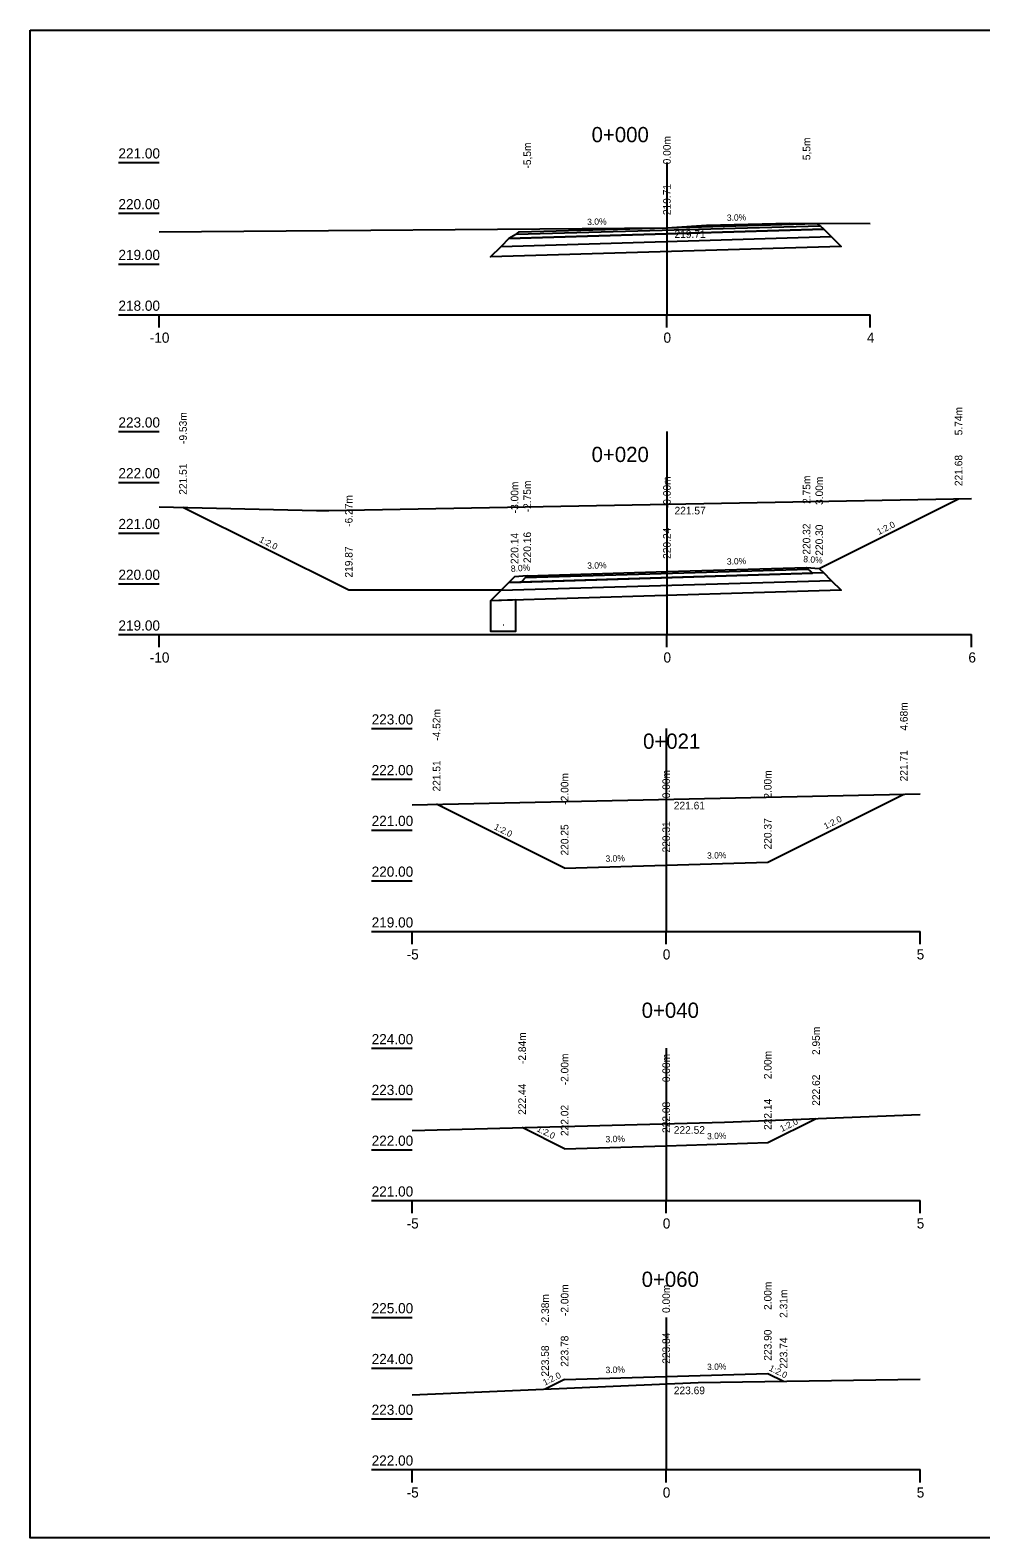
# Model space of a CAD drawing. Extents: x -577111.4 to -577069.4, y -1164371.9 to -1164342.2.
# Drawn here: x -577111.42 to -577092.7, y -1164371.89 to -1164342.19 of the extents above; entities that cross this region are included whole.
import ezdxf

# ---------------------------------------------------------------- set-up
doc = ezdxf.new("R2010")
doc.units = 0
for name, color, linetype in [('16', 7, 'Continuous'), ('21', 7, 'Continuous'), ('28', 7, 'Continuous'), ('59', 7, 'Continuous'), ('Body pricny rez', 7, 'Continuous'), ('Popis pricneho profilu', 7, 'Continuous'), ('Rámy', 7, 'Continuous')]:
    doc.layers.add(name, color=color, linetype=linetype)

msp = doc.modelspace()

# ---------------------------------------------------------------- linework, layer by layer
for points in [[(-577108.878, -1164346.165), (-577098.879, -1164346.086), (-577098.097, -1164346.034), (-577096.456, -1164345.995), (-577094.878, -1164345.998)], [(-577108.878, -1164351.583), (-577105.776, -1164351.655), (-577105.533, -1164351.657), (-577092.878, -1164351.419)], [(-577102.143, -1164353.226), (-577105.143, -1164353.226), (-577108.407, -1164351.594)], [(-577095.878, -1164352.795), (-577093.135, -1164351.424)], [(-577102.1, -1164353.907), (-577102.099, -1164353.907)], [(-577103.892, -1164357.45), (-577093.892, -1164357.234)], [(-577096.892, -1164358.581), (-577094.213, -1164357.241)], [(-577100.892, -1164358.701), (-577103.413, -1164357.44)], [(-577100.892, -1164358.701), (-577098.892, -1164358.641), (-577096.892, -1164358.581)], [(-577103.892, -1164363.865), (-577101.426, -1164363.801), (-577097.746, -1164363.703), (-577093.892, -1164363.55)], [(-577100.892, -1164364.227), (-577101.728, -1164363.809)], [(-577096.892, -1164364.107), (-577095.941, -1164363.631)], [(-577100.892, -1164364.227), (-577098.892, -1164364.167), (-577096.892, -1164364.107)], [(-577103.892, -1164369.078), (-577098.262, -1164368.835), (-577093.892, -1164368.766)], [(-577100.892, -1164368.773), (-577101.276, -1164368.966)], [(-577100.892, -1164368.773), (-577098.892, -1164368.713), (-577096.892, -1164368.653)], [(-577096.892, -1164368.653), (-577096.581, -1164368.809)]]:
    msp.add_lwpolyline(points)
for points in [[(-577098.878, -1164346.086), (-577095.935, -1164345.998), (-577095.856, -1164346.053), (-577101.856, -1164346.221), (-577101.786, -1164346.168)], [(-577095.642, -1164346.259), (-577095.448, -1164346.454), (-577102.35, -1164346.661), (-577102.143, -1164346.454)], [(-577101.989, -1164346.3), (-577102.143, -1164346.454), (-577095.642, -1164346.259), (-577095.788, -1164346.114)], [(-577101.856, -1164346.221), (-577101.989, -1164346.3), (-577095.788, -1164346.114), (-577095.856, -1164346.053)], [(-577101.669, -1164352.982), (-577101.751, -1164353.064), (-577096.011, -1164352.892), (-577096.089, -1164352.814)], [(-577098.878, -1164352.858), (-577096.128, -1164352.775), (-577096.089, -1164352.814), (-577101.669, -1164352.982), (-577101.628, -1164352.94)], [(-577096.128, -1164352.775), (-577095.878, -1164352.795), (-577095.788, -1164352.885), (-577096.011, -1164352.892)], [(-577095.642, -1164353.031), (-577095.448, -1164353.225), (-577102.35, -1164353.432), (-577102.143, -1164353.226)], [(-577101.989, -1164353.071), (-577102.143, -1164353.226), (-577095.642, -1164353.031), (-577095.788, -1164352.885)], [(-577101.628, -1164352.94), (-577101.878, -1164352.96), (-577101.989, -1164353.071), (-577101.751, -1164353.064)], [(-577102.35, -1164353.432), (-577102.35, -1164354.032), (-577101.85, -1164354.032), (-577101.85, -1164353.417)]]:
    msp.add_lwpolyline(points, close=True)
at = {"layer": '16'}
for p, q in [((-577108.878, -1164347.8), (-577094.878, -1164347.8)), ((-577108.878, -1164354.1), (-577092.878, -1164354.1)), ((-577103.892, -1164359.949), (-577093.892, -1164359.949)), ((-577103.892, -1164365.249), (-577093.892, -1164365.249)), ((-577103.892, -1164370.549), (-577093.892, -1164370.549))]:
    msp.add_line(p, q, dxfattribs=at)
at = {"layer": '21'}
for p, q in [((-577109.678, -1164344.8), (-577108.878, -1164344.8)), ((-577109.678, -1164345.8), (-577108.878, -1164345.8)), ((-577109.678, -1164346.8), (-577108.878, -1164346.8)), ((-577109.678, -1164347.8), (-577108.878, -1164347.8)), ((-577109.678, -1164350.1), (-577108.878, -1164350.1)), ((-577109.678, -1164351.1), (-577108.878, -1164351.1)), ((-577109.678, -1164352.1), (-577108.878, -1164352.1)), ((-577109.678, -1164353.1), (-577108.878, -1164353.1)), ((-577109.678, -1164354.1), (-577108.878, -1164354.1)), ((-577104.692, -1164355.949), (-577103.892, -1164355.949)), ((-577104.692, -1164356.949), (-577103.892, -1164356.949)), ((-577104.692, -1164357.949), (-577103.892, -1164357.949)), ((-577104.692, -1164358.949), (-577103.892, -1164358.949)), ((-577104.692, -1164359.949), (-577103.892, -1164359.949)), ((-577104.692, -1164362.249), (-577103.892, -1164362.249)), ((-577104.692, -1164363.249), (-577103.892, -1164363.249)), ((-577104.692, -1164364.249), (-577103.892, -1164364.249)), ((-577104.692, -1164365.249), (-577103.892, -1164365.249)), ((-577104.692, -1164367.549), (-577103.892, -1164367.549)), ((-577104.692, -1164368.549), (-577103.892, -1164368.549)), ((-577104.692, -1164369.549), (-577103.892, -1164369.549)), ((-577104.692, -1164370.549), (-577103.892, -1164370.549))]:
    msp.add_line(p, q, dxfattribs=at)
at = {"layer": '28'}
for p, q in [((-577098.878, -1164344.8), (-577098.878, -1164347.8)), ((-577098.878, -1164350.1), (-577098.878, -1164354.1)), ((-577098.892, -1164355.949), (-577098.892, -1164359.949)), ((-577098.892, -1164362.249), (-577098.892, -1164365.249)), ((-577098.892, -1164367.549), (-577098.892, -1164370.549))]:
    msp.add_line(p, q, dxfattribs=at)
at = {"layer": '59'}
for p, q in [((-577108.878, -1164348.05), (-577108.878, -1164347.8)), ((-577098.878, -1164348.05), (-577098.878, -1164347.8)), ((-577094.878, -1164348.05), (-577094.878, -1164347.8)), ((-577108.878, -1164354.35), (-577108.878, -1164354.1)), ((-577098.878, -1164354.35), (-577098.878, -1164354.1)), ((-577092.878, -1164354.35), (-577092.878, -1164354.1)), ((-577103.892, -1164360.199), (-577103.892, -1164359.949)), ((-577098.892, -1164360.199), (-577098.892, -1164359.949)), ((-577093.892, -1164360.199), (-577093.892, -1164359.949)), ((-577103.892, -1164365.499), (-577103.892, -1164365.249)), ((-577098.892, -1164365.499), (-577098.892, -1164365.249)), ((-577093.892, -1164365.499), (-577093.892, -1164365.249)), ((-577103.892, -1164370.799), (-577103.892, -1164370.549)), ((-577098.892, -1164370.799), (-577098.892, -1164370.549)), ((-577093.892, -1164370.799), (-577093.892, -1164370.549))]:
    msp.add_line(p, q, dxfattribs=at)
at = {"layer": 'Rámy'}
msp.add_line((-577111.416, -1164371.893), (-577111.416, -1164370.752), dxfattribs=at)
msp.add_lwpolyline([(-577111.416, -1164342.193), (-577069.416, -1164342.193), (-577069.416, -1164371.893), (-577111.416, -1164371.893)], close=True, dxfattribs=at)

# ---------------------------------------------------------------- texts
for s, p in [('0+000', (-577100.361, -1164344.4)), ('0+020', (-577100.361, -1164350.7)), ('0+021', (-577099.348, -1164356.349)), ('0+040', (-577099.375, -1164361.649)), ('0+060', (-577099.375, -1164366.949))]:
    msp.add_text(s, height=0.3).set_placement(p)
for rotation, p in [(26.5651, (-577094.704, -1164352.139)), (333.4349, (-577106.917, -1164352.269)), (333.4349, (-577102.295, -1164357.929)), (26.5651, (-577095.751, -1164357.94)), (333.4349, (-577101.452, -1164363.877)), (26.5651, (-577096.614, -1164363.898)), (333.4349, (-577096.879, -1164368.59)), (26.5651, (-577101.282, -1164368.898))]:
    msp.add_text('1:2.0', height=0.125, rotation=rotation).set_placement(p)
at = {"layer": '16'}
for s, rotation, p in [('3.0%', 1.7184, (-577100.446, -1164346.033)), ('3.0%', 1.7184, (-577097.696, -1164345.951)), ('8.0%', 355.4261, (-577096.196, -1164352.67)), ('8.0%', 4.5739, (-577101.946, -1164352.866)), ('3.0%', 1.7184, (-577100.446, -1164352.805)), ('3.0%', 1.7184, (-577097.696, -1164352.722)), ('3.0%', 1.7184, (-577100.085, -1164358.576)), ('3.0%', 1.7184, (-577098.085, -1164358.516)), ('3.0%', 1.7184, (-577100.085, -1164364.103)), ('3.0%', 1.7184, (-577098.085, -1164364.043)), ('3.0%', 1.7184, (-577100.085, -1164368.649)), ('3.0%', 1.7184, (-577098.085, -1164368.589))]:
    msp.add_text(s, height=0.125, rotation=rotation, dxfattribs=at).set_placement(p)
at = {"layer": '21'}
for s, p in [('221.00', (-577109.678, -1164344.72)), ('220.00', (-577109.678, -1164345.72)), ('219.00', (-577109.678, -1164346.72)), ('218.00', (-577109.678, -1164347.72)), ('-10', (-577109.061, -1164348.35)), ('0', (-577098.945, -1164348.35)), ('4', (-577094.94, -1164348.35)), ('223.00', (-577109.678, -1164350.02)), ('222.00', (-577109.678, -1164351.02)), ('221.00', (-577109.678, -1164352.02)), ('220.00', (-577109.678, -1164353.02)), ('219.00', (-577109.678, -1164354.02)), ('-10', (-577109.061, -1164354.65)), ('0', (-577098.945, -1164354.65)), ('6', (-577092.941, -1164354.65)), ('223.00', (-577104.692, -1164355.869)), ('222.00', (-577104.692, -1164356.869)), ('221.00', (-577104.692, -1164357.869)), ('220.00', (-577104.692, -1164358.869)), ('219.00', (-577104.692, -1164359.869)), ('-5', (-577104.003, -1164360.499)), ('0', (-577098.959, -1164360.499)), ('5', (-577093.959, -1164360.499)), ('224.00', (-577104.692, -1164362.169)), ('223.00', (-577104.692, -1164363.169)), ('222.00', (-577104.692, -1164364.169)), ('221.00', (-577104.692, -1164365.169)), ('-5', (-577104.003, -1164365.799)), ('0', (-577098.959, -1164365.799)), ('5', (-577093.959, -1164365.799)), ('225.00', (-577104.692, -1164367.469)), ('224.00', (-577104.692, -1164368.469)), ('223.00', (-577104.692, -1164369.469)), ('222.00', (-577104.692, -1164370.469)), ('-5', (-577104.003, -1164371.099)), ('0', (-577098.959, -1164371.099)), ('5', (-577093.959, -1164371.099))]:
    msp.add_text(s, height=0.2, dxfattribs=at).set_placement(p)
at = {"layer": '59'}
for s, p in [('219.71', (-577098.728, -1164346.286)), ('221.57', (-577098.728, -1164351.732)), ('221.61', (-577098.742, -1164357.542)), ('222.52', (-577098.742, -1164363.933)), ('223.69', (-577098.742, -1164369.063))]:
    msp.add_text(s, height=0.15, dxfattribs=at).set_placement(p)
at = {"layer": 'Body pricny rez'}
for p in [(-577096.128, -1164346.004), (-577095.878, -1164346.024), (-577101.878, -1164346.189), (-577101.628, -1164346.169), (-577098.878, -1164346.087), (-577108.408, -1164351.594), (-577093.135, -1164351.424), (-577098.878, -1164352.858), (-577096.128, -1164352.776), (-577095.878, -1164352.796), (-577101.878, -1164352.961), (-577101.628, -1164352.941), (-577105.144, -1164353.226), (-577102.1, -1164353.908), (-577094.214, -1164357.242), (-577103.414, -1164357.44), (-577100.892, -1164358.701), (-577098.892, -1164358.641), (-577096.892, -1164358.581), (-577101.728, -1164363.809), (-577095.942, -1164363.632), (-577096.892, -1164364.107), (-577100.892, -1164364.227), (-577098.892, -1164364.167), (-577100.892, -1164368.774), (-577098.892, -1164368.714), (-577096.892, -1164368.654), (-577096.582, -1164368.809), (-577101.277, -1164368.966)]:
    msp.add_text('+', height=0.001, dxfattribs=at).set_placement(p)
at = {"layer": 'Popis pricneho profilu'}
for s, p in [('-5,5m', (-577101.553, -1164344.919)), ('0.00m', (-577098.803, -1164344.836)), ('5,5m', (-577096.053, -1164344.754)), ('219.71', (-577098.803, -1164345.836)), ('-9.53m', (-577108.332, -1164350.344)), ('5.74m', (-577093.06, -1164350.174)), ('221.51', (-577108.332, -1164351.344)), ('221.68', (-577093.06, -1164351.174)), ('-0.00m', (-577098.803, -1164351.608)), ('2.75m', (-577096.053, -1164351.525)), ('3.00m', (-577095.803, -1164351.545)), ('-6.27m', (-577105.068, -1164351.976)), ('-3.00m', (-577101.803, -1164351.71)), ('-2.75m', (-577101.553, -1164351.69)), ('220.32', (-577096.053, -1164352.525)), ('220.30', (-577095.803, -1164352.545)), ('220.14', (-577101.803, -1164352.71)), ('220.16', (-577101.553, -1164352.69)), ('220.24', (-577098.803, -1164352.608)), ('219.87', (-577105.068, -1164352.976)), ('4.68m', (-577094.138, -1164355.991)), ('-4.52m', (-577103.338, -1164356.19)), ('221.71', (-577094.138, -1164356.991)), ('221.51', (-577103.338, -1164357.19)), ('-2.00m', (-577100.817, -1164357.451)), ('-0.00m', (-577098.817, -1164357.391)), ('2.00m', (-577096.817, -1164357.331)), ('220.25', (-577100.817, -1164358.451)), ('220.31', (-577098.817, -1164358.391)), ('220.37', (-577096.817, -1164358.331)), ('-2.84m', (-577101.653, -1164362.559)), ('2.95m', (-577095.866, -1164362.381)), ('2.00m', (-577096.817, -1164362.857)), ('-2.00m', (-577100.817, -1164362.977)), ('0.00m', (-577098.817, -1164362.917)), ('222.44', (-577101.653, -1164363.559)), ('222.62', (-577095.866, -1164363.381)), ('222.14', (-577096.817, -1164363.857)), ('222.02', (-577100.817, -1164363.977)), ('222.08', (-577098.817, -1164363.917)), ('-2.38m', (-577101.201, -1164367.716)), ('-2.00m', (-577100.817, -1164367.523)), ('0.00m', (-577098.817, -1164367.463)), ('2.00m', (-577096.817, -1164367.403)), ('2.31m', (-577096.506, -1164367.559)), ('223.78', (-577100.817, -1164368.523)), ('223.84', (-577098.817, -1164368.463)), ('223.90', (-577096.817, -1164368.403)), ('223.74', (-577096.506, -1164368.559)), ('223.58', (-577101.201, -1164368.716))]:
    msp.add_text(s, height=0.15, rotation=90, dxfattribs=at).set_placement(p)

doc.saveas('drawing.dxf')
